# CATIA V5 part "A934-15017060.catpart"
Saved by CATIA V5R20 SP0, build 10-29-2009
Part number: A934-15017060
Source: Unknown
Property "A": "110.000"
Property "ARTICLENO": "A934-15017060"
Property "B": "30.000"
Property "BOMINFO": "A934-15017060"
Property "CODE": "A934-15017060"
Property "L": "170.000"
Property "L1": "127.860"
Property "LINA": "A934-15017060"
Property "NB": "A934-15017060"
Property "NBSYN": "$CODE."
Property "NN": "A934"
Property "NT": "VDI 3357 H-Type Cam Drivers, self-lubricating"
Property "SUPPLIER": "CF"
Property "T": "60.000"
Property "W": "150.000"
Bounding box of the stored display mesh (mm): x 0 to 170, y 0 to 60, z -150 to 0
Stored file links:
  C:\Users\Utente\Desktop\3D files A934\A934-15017060.catpart
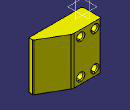
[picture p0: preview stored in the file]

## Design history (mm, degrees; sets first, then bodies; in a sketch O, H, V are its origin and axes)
Body1 "Geometry.1" (main body)
  Solid1 "A934-15017060.catpart": solid without history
